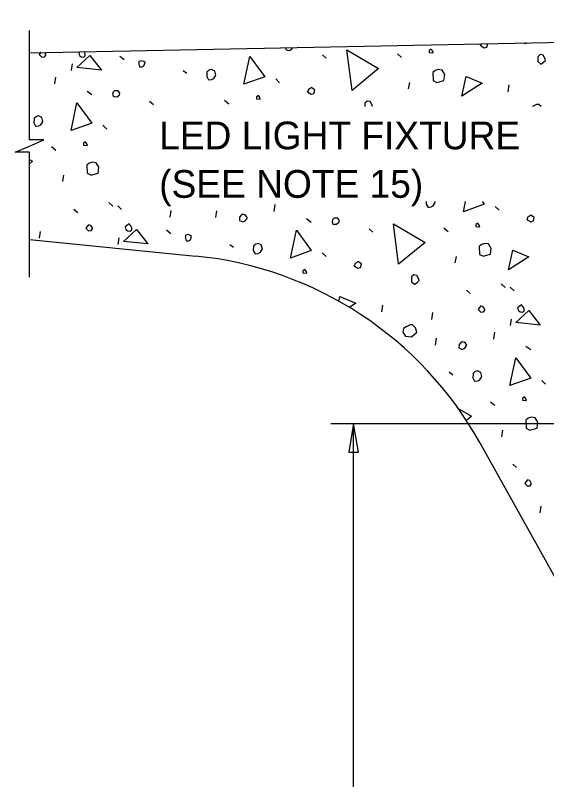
# Model space of a CAD drawing. Extents: x -1660015.2 to -1659984.9, y 2580594.2 to 2580616.7.
# Drawn here: x -1660014.771 to -1660011.876, y 2580610.058 to 2580614.22 of the extents above; entities that cross this region are included whole.
import ezdxf

# ---------------------------------------------------------------- set-up
doc = ezdxf.new("R2010")
doc.units = 0
for name, color, linetype in [('Miscellaneous', 7, 'Continuous'), ('Miscellaneous3', 7, 'Continuous'), ('SheetLines_dp', 7, 'Continuous')]:
    doc.layers.add(name, color=color, linetype=linetype)

msp = doc.modelspace()

# ---------------------------------------------------------------- linework, layer by layer
at = {"layer": 'Miscellaneous'}
for p, q in [((-1660013.4131, 2580614.0414), (-1660013.4121, 2580614.0407)), ((-1660014.2004, 2580613.9977), (-1660014.177, 2580613.9781)), ((-1660013.0968, 2580614.0035), (-1660013.0765, 2580613.9857)), ((-1660012.6894, 2580614.0092), (-1660012.666, 2580613.9896)), ((-1660014.4641, 2580613.9193), (-1660014.458, 2580613.9546)), ((-1660013.8558, 2580613.9192), (-1660013.8361, 2580613.9038)), ((-1660014.5556, 2580613.8456), (-1660014.5502, 2580613.8833)), ((-1660013.3517, 2580613.8731), (-1660013.3307, 2580613.8528)), ((-1660012.6279, 2580613.8186), (-1660012.6219, 2580613.8539)), ((-1660012.0855, 2580613.8034), (-1660012.0801, 2580613.8411)), ((-1660014.3797, 2580613.8073), (-1660014.3539, 2580613.7883)), ((-1660014.0386, 2580613.7512), (-1660014.0182, 2580613.7333)), ((-1660013.6311, 2580613.7568), (-1660013.6078, 2580613.7372)), ((-1660014.2935, 2580613.6208), (-1660014.2725, 2580613.6005)), ((-1660014.5729, 2580613.5045), (-1660014.5495, 2580613.4849)), ((-1660014.5115, 2580613.3139), (-1660014.5054, 2580613.3492)), ((-1660013.2686, 2580613.225), (-1660013.2686, 2580613.2251)), ((-1660014.4508, 2580613.1645), (-1660014.4304, 2580613.1467)), ((-1660014.2609, 2580613.1998), (-1660014.24, 2580613.1796)), ((-1660014.2121, 2580613.1819), (-1660014.1912, 2580613.1616)), ((-1660013.3602, 2580613.1513), (-1660013.3548, 2580613.189)), ((-1660012.1563, 2580613.1789), (-1660012.1353, 2580613.1586)), ((-1660013.9267, 2580613.1212), (-1660013.9206, 2580613.1564)), ((-1660013.6774, 2580613.1181), (-1660013.672, 2580613.1558)), ((-1660013.1843, 2580613.113), (-1660013.1585, 2580613.0941)), ((-1660014.6385, 2580613.0055), (-1660014.6331, 2580613.0432)), ((-1660013.9467, 2580613.0511), (-1660013.9234, 2580613.0315)), ((-1660012.8431, 2580613.0569), (-1660012.8228, 2580613.0391)), ((-1660012.4357, 2580613.0626), (-1660012.4123, 2580613.043)), ((-1660014.2104, 2580612.9727), (-1660014.2043, 2580613.008)), ((-1660013.6022, 2580612.9726), (-1660013.5825, 2580612.9572)), ((-1660013.0981, 2580612.9265), (-1660013.0771, 2580612.9062)), ((-1660012.3743, 2580612.872), (-1660012.3682, 2580612.9072)), ((-1660012.1237, 2580612.7579), (-1660012.1028, 2580612.7377)), ((-1660012.3136, 2580612.7226), (-1660012.2932, 2580612.7047)), ((-1660012.0749, 2580612.74), (-1660012.054, 2580612.7197)), ((-1660012.7737, 2580612.6045), (-1660012.7682, 2580612.6422)), ((-1660012.5013, 2580612.5636), (-1660012.4959, 2580612.6013)), ((-1660012.0732, 2580612.5308), (-1660012.0671, 2580612.566)), ((-1660012.482, 2580612.4238), (-1660012.4765, 2580612.4615)), ((-1660012.1648, 2580612.4571), (-1660012.1593, 2580612.4948)), ((-1660011.9889, 2580612.4188), (-1660011.9631, 2580612.3998)), ((-1660012.4067, 2580612.2783), (-1660012.3871, 2580612.2629)), ((-1660011.9026, 2580612.2322), (-1660011.8817, 2580612.212)), ((-1660012.1821, 2580612.116), (-1660012.1587, 2580612.0963)), ((-1660012.1206, 2580611.9254), (-1660012.1146, 2580611.9606)), ((-1660012.0599, 2580611.776), (-1660012.0396, 2580611.7581)), ((-1660011.9111, 2580611.5105), (-1660011.9057, 2580611.5481))]:
    msp.add_line(p, q, dxfattribs=at)
for points in [[(-1660013.2985, 2580614.0437), (-1660013.2988, 2580614.0426), (-1660013.2962, 2580614.0329)], [(-1660013.2962, 2580614.0329), (-1660013.2901, 2580614.0294), (-1660013.2743, 2580614.0284), (-1660013.2617, 2580614.0396), (-1660013.2601, 2580614.0445)], [(-1660012.2339, 2580614.065), (-1660012.2353, 2580614.0532), (-1660012.2366, 2580614.058)], [(-1660012.2353, 2580614.0532), (-1660012.2169, 2580614.0426), (-1660012.2024, 2580614.0465), (-1660012.1973, 2580614.0657)], [(-1660011.9947, 2580614.0633), (-1660011.9955, 2580614.0698)], [(-1660011.9867, 2580614.0699), (-1660011.9947, 2580614.0633)], [(-1660014.6402, 2580614.0067), (-1660014.626, 2580613.9924), (-1660014.6109, 2580613.9938), (-1660014.6031, 2580614.0037), (-1660014.6044, 2580614.0085), (-1660014.6103, 2580614.0175)], [(-1660014.6321, 2580614.017), (-1660014.6325, 2580614.0165), (-1660014.6402, 2580614.0067)], [(-1660014.4346, 2580613.9349), (-1660014.3641, 2580614.0004), (-1660014.3016, 2580613.9214), (-1660014.4346, 2580613.9349)], [(-1660014.4181, 2580614.0213), (-1660014.425, 2580614.0152), (-1660014.4212, 2580614.0007)], [(-1660014.4212, 2580614.0007), (-1660014.4113, 2580613.9929), (-1660014.398, 2580613.9913), (-1660014.3896, 2580613.9988), (-1660014.3898, 2580614.0091), (-1660014.3954, 2580614.0205), (-1660014.3963, 2580614.0217)], [(-1660013.5253, 2580613.8447), (-1660013.4932, 2580613.9957), (-1660013.4119, 2580613.8854), (-1660013.5253, 2580613.8447)], [(-1660012.9365, 2580613.811), (-1660012.9644, 2580614.0312), (-1660012.7923, 2580613.9298), (-1660012.9365, 2580613.811)], [(-1660012.5154, 2580614.017), (-1660012.4942, 2580614.0149), (-1660012.4968, 2580614.0245), (-1660012.5048, 2580614.0353), (-1660012.5156, 2580614.0273), (-1660012.5154, 2580614.017)], [(-1660011.9249, 2580613.9863), (-1660011.9252, 2580613.9681), (-1660011.9086, 2580613.9544), (-1660011.893, 2580613.9638), (-1660011.8828, 2580613.9742), (-1660011.8861, 2580613.9863), (-1660011.8954, 2580614.0019), (-1660011.9118, 2580614.0053), (-1660011.9244, 2580613.9941), (-1660011.9249, 2580613.9863)], [(-1660014.0977, 2580613.9527), (-1660014.0939, 2580613.9382), (-1660014.0811, 2580613.9391), (-1660014.0697, 2580613.9447), (-1660014.0639, 2580613.9618), (-1660014.0707, 2580613.9677), (-1660014.0823, 2580613.9724), (-1660014.0968, 2580613.9685), (-1660014.0977, 2580613.9527)], [(-1660013.7265, 2580613.9099), (-1660013.7279, 2580613.8862), (-1660013.7179, 2580613.8682), (-1660013.7004, 2580613.8703), (-1660013.6889, 2580613.8759), (-1660013.6783, 2580613.8943), (-1660013.6841, 2580613.916), (-1660013.7019, 2580613.9242), (-1660013.7139, 2580613.921), (-1660013.7265, 2580613.9099)], [(-1660012.4966, 2580613.9081), (-1660012.4953, 2580613.8645), (-1660012.4745, 2580613.8545), (-1660012.4624, 2580613.8577), (-1660012.4359, 2580613.8649), (-1660012.4316, 2580613.8971), (-1660012.4459, 2580613.9217), (-1660012.4648, 2580613.9244), (-1660012.4841, 2580613.9192), (-1660012.4966, 2580613.9081)], [(-1660012.338, 2580613.7798), (-1660012.315, 2580613.8869), (-1660012.2276, 2580613.8508), (-1660012.338, 2580613.7798)], [(-1660014.238, 2580613.7806), (-1660014.2318, 2580613.777), (-1660014.216, 2580613.7761), (-1660014.2035, 2580613.7872), (-1660014.2006, 2580613.7958), (-1660014.2093, 2580613.809), (-1660014.2299, 2580613.8086), (-1660014.2383, 2580613.8012), (-1660014.2405, 2580613.7902), (-1660014.238, 2580613.7806)], [(-1660013.1771, 2580613.8009), (-1660013.1587, 2580613.7902), (-1660013.1442, 2580613.7941), (-1660013.1391, 2580613.8136), (-1660013.1581, 2580613.8266), (-1660013.1664, 2580613.8192), (-1660013.1755, 2580613.8142), (-1660013.1771, 2580613.8009), (-1660013.1783, 2580613.8057)], [(-1660013.4572, 2580613.7646), (-1660013.436, 2580613.7625), (-1660013.4385, 2580613.7722), (-1660013.4466, 2580613.783), (-1660013.4574, 2580613.7749), (-1660013.4572, 2580613.7646)], [(-1660012.8248, 2580613.7225), (-1660012.8278, 2580613.734), (-1660012.8372, 2580613.7496), (-1660012.8536, 2580613.7529), (-1660012.8662, 2580613.7418), (-1660012.8666, 2580613.7339)], [(-1660014.467, 2580613.5924), (-1660014.435, 2580613.7433), (-1660014.3537, 2580613.6331), (-1660014.467, 2580613.5924)], [(-1660012.8666, 2580613.7339), (-1660012.8668, 2580613.7225)], [(-1660011.907, 2580613.7225), (-1660011.9194, 2580613.7341), (-1660011.9321, 2580613.7333), (-1660011.9526, 2580613.7226), (-1660011.9528, 2580613.7225)], [(-1660014.6683, 2580613.6575), (-1660014.6697, 2580613.6338), (-1660014.6597, 2580613.6158), (-1660014.6421, 2580613.6179), (-1660014.6307, 2580613.6236), (-1660014.6201, 2580613.642), (-1660014.6259, 2580613.6637), (-1660014.6436, 2580613.6719), (-1660014.6557, 2580613.6686), (-1660014.6683, 2580613.6575)], [(-1660014.399, 2580613.5123), (-1660014.3777, 2580613.5102), (-1660014.3803, 2580613.5198), (-1660014.3884, 2580613.5306), (-1660014.3992, 2580613.5226), (-1660014.399, 2580613.5123)], [(-1660014.6931, 2580613.4353), (-1660014.6759, 2580613.4251), (-1660014.6931, 2580613.4109)], [(-1660014.3802, 2580613.4034), (-1660014.3788, 2580613.3598), (-1660014.3581, 2580613.3498), (-1660014.346, 2580613.3531), (-1660014.3194, 2580613.3602), (-1660014.3151, 2580613.3924), (-1660014.3295, 2580613.417), (-1660014.3483, 2580613.4197), (-1660014.3676, 2580613.4145), (-1660014.3802, 2580613.4034)], [(-1660012.5317, 2580613.2051), (-1660012.5325, 2580613.1919), (-1660012.5225, 2580613.1739), (-1660012.5049, 2580613.176), (-1660012.4935, 2580613.1817), (-1660012.4829, 2580613.2), (-1660012.4842, 2580613.2051)], [(-1660012.3299, 2580613.1505), (-1660012.3183, 2580613.2051)], [(-1660012.2268, 2580613.2051), (-1660012.2165, 2580613.1912), (-1660012.3299, 2580613.1505)], [(-1660013.5489, 2580613.1215), (-1660013.5492, 2580613.1033), (-1660013.5315, 2580613.0951), (-1660013.5176, 2580613.1014), (-1660013.5064, 2580613.1173), (-1660013.5144, 2580613.1281), (-1660013.5212, 2580613.1341), (-1660013.5322, 2580613.1363), (-1660013.537, 2580613.135), (-1660013.5489, 2580613.1215)], [(-1660011.9816, 2580613.1066), (-1660011.9633, 2580613.096), (-1660011.9488, 2580613.0999), (-1660011.9436, 2580613.1194), (-1660011.9627, 2580613.1324), (-1660011.971, 2580613.125), (-1660011.98, 2580613.12), (-1660011.9816, 2580613.1066), (-1660011.9829, 2580613.1114)], [(-1660014.3865, 2580613.0601), (-1660014.3723, 2580613.0458), (-1660014.3572, 2580613.0472), (-1660014.3495, 2580613.0571), (-1660014.3508, 2580613.0619), (-1660014.3595, 2580613.0751), (-1660014.3711, 2580613.0797), (-1660014.3788, 2580613.0699), (-1660014.3865, 2580613.0601)], [(-1660014.1675, 2580613.0541), (-1660014.1577, 2580613.0463), (-1660014.1443, 2580613.0447), (-1660014.1359, 2580613.0522), (-1660014.1361, 2580613.0625), (-1660014.1418, 2580613.0739), (-1660014.1498, 2580613.0847), (-1660014.163, 2580613.076), (-1660014.1714, 2580613.0685), (-1660014.1675, 2580613.0541)], [(-1660013.0425, 2580613.0863), (-1660013.0364, 2580613.0828), (-1660013.0206, 2580613.0818), (-1660013.0081, 2580613.093), (-1660013.0052, 2580613.1015), (-1660013.0139, 2580613.1147), (-1660013.0345, 2580613.1144), (-1660013.0429, 2580613.1069), (-1660013.0451, 2580613.096), (-1660013.0425, 2580613.0863)], [(-1660012.6828, 2580612.8644), (-1660012.7108, 2580613.0846), (-1660012.5387, 2580612.9832), (-1660012.6828, 2580612.8644)], [(-1660012.2618, 2580613.0703), (-1660012.2405, 2580613.0683), (-1660012.2431, 2580613.0779), (-1660012.2512, 2580613.0887), (-1660012.262, 2580613.0807), (-1660012.2618, 2580613.0703)], [(-1660014.181, 2580612.9883), (-1660014.1105, 2580613.0538), (-1660014.0479, 2580612.9748), (-1660014.181, 2580612.9883)], [(-1660013.2716, 2580612.8981), (-1660013.2396, 2580613.049), (-1660013.1583, 2580612.9388), (-1660013.2716, 2580612.8981)], [(-1660013.8441, 2580613.0061), (-1660013.8402, 2580612.9916), (-1660013.8275, 2580612.9925), (-1660013.8161, 2580612.9981), (-1660013.8103, 2580613.0152), (-1660013.8171, 2580613.0211), (-1660013.8287, 2580613.0258), (-1660013.8431, 2580613.0219), (-1660013.8441, 2580613.0061)], [(-1660013.4728, 2580612.9633), (-1660013.4743, 2580612.9396), (-1660013.4643, 2580612.9216), (-1660013.4467, 2580612.9237), (-1660013.4353, 2580612.9293), (-1660013.4247, 2580612.9477), (-1660013.4305, 2580612.9694), (-1660013.4482, 2580612.9776), (-1660013.4603, 2580612.9744), (-1660013.4728, 2580612.9633)], [(-1660012.243, 2580612.9615), (-1660012.2416, 2580612.9179), (-1660012.2209, 2580612.9079), (-1660012.2088, 2580612.9111), (-1660012.1822, 2580612.9183), (-1660012.1779, 2580612.9505), (-1660012.1923, 2580612.9751), (-1660012.2111, 2580612.9778), (-1660012.2304, 2580612.9726), (-1660012.243, 2580612.9615)], [(-1660012.0844, 2580612.8332), (-1660012.0613, 2580612.9403), (-1660011.974, 2580612.9042), (-1660012.0844, 2580612.8332)], [(-1660012.9234, 2580612.8542), (-1660012.905, 2580612.8436), (-1660012.8905, 2580612.8475), (-1660012.8854, 2580612.867), (-1660012.9044, 2580612.88), (-1660012.9128, 2580612.8726), (-1660012.9218, 2580612.8676), (-1660012.9234, 2580612.8542), (-1660012.9247, 2580612.8591)], [(-1660013.2036, 2580612.818), (-1660013.1823, 2580612.8159), (-1660013.1849, 2580612.8256), (-1660013.193, 2580612.8364), (-1660013.2037, 2580612.8283), (-1660013.2036, 2580612.818)], [(-1660012.613, 2580612.7873), (-1660012.6133, 2580612.7691), (-1660012.5967, 2580612.7554), (-1660012.5811, 2580612.7648), (-1660012.571, 2580612.7753), (-1660012.5742, 2580612.7873), (-1660012.5836, 2580612.803), (-1660012.6, 2580612.8063), (-1660012.6125, 2580612.7952), (-1660012.613, 2580612.7873)], [(-1660013.0084, 2580612.6632), (-1660013.0031, 2580612.688), (-1660012.9158, 2580612.6518), (-1660012.9506, 2580612.6294)], [(-1660012.2493, 2580612.6182), (-1660012.2351, 2580612.6038), (-1660012.22, 2580612.6053), (-1660012.2123, 2580612.6151), (-1660012.2136, 2580612.62), (-1660012.2223, 2580612.6332), (-1660012.2339, 2580612.6378), (-1660012.2416, 2580612.628), (-1660012.2493, 2580612.6182)], [(-1660012.0303, 2580612.6121), (-1660012.0205, 2580612.6044), (-1660012.0071, 2580612.6028), (-1660011.9988, 2580612.6103), (-1660011.9989, 2580612.6206), (-1660012.0046, 2580612.632), (-1660012.0126, 2580612.6428), (-1660012.0258, 2580612.6341), (-1660012.0342, 2580612.6266), (-1660012.0303, 2580612.6121)], [(-1660012.0438, 2580612.5464), (-1660011.9733, 2580612.6119), (-1660011.9107, 2580612.5329), (-1660012.0438, 2580612.5464)], [(-1660012.659, 2580612.4954), (-1660012.6453, 2580612.4732), (-1660012.6131, 2580612.4689), (-1660012.5838, 2580612.4949), (-1660012.5903, 2580612.519), (-1660012.6076, 2580612.5351), (-1660012.6203, 2580612.5343), (-1660012.6407, 2580612.5236), (-1660012.6563, 2580612.5143), (-1660012.659, 2580612.4954)], [(-1660012.3535, 2580612.4272), (-1660012.3538, 2580612.409), (-1660012.336, 2580612.4008), (-1660012.3222, 2580612.4071), (-1660012.3109, 2580612.4231), (-1660012.319, 2580612.4339), (-1660012.3258, 2580612.4398), (-1660012.3367, 2580612.442), (-1660012.3416, 2580612.4407), (-1660012.3535, 2580612.4272)], [(-1660012.0762, 2580612.2039), (-1660012.0442, 2580612.3548), (-1660011.9629, 2580612.2446), (-1660012.0762, 2580612.2039)], [(-1660012.2774, 2580612.269), (-1660012.2788, 2580612.2453), (-1660012.2688, 2580612.2273), (-1660012.2513, 2580612.2294), (-1660012.2399, 2580612.2351), (-1660012.2293, 2580612.2534), (-1660012.2351, 2580612.2752), (-1660012.2528, 2580612.2834), (-1660012.2649, 2580612.2801), (-1660012.2774, 2580612.269)], [(-1660012.0082, 2580612.1237), (-1660011.9869, 2580612.1217), (-1660011.9895, 2580612.1313), (-1660011.9975, 2580612.1421), (-1660012.0083, 2580612.134), (-1660012.0082, 2580612.1237)], [(-1660012.3583, 2580612.0798), (-1660012.285, 2580612.0366), (-1660012.3131, 2580612.0135)], [(-1660011.9893, 2580612.0149), (-1660011.988, 2580611.9713), (-1660011.9672, 2580611.9613), (-1660011.9551, 2580611.9645), (-1660011.9286, 2580611.9717), (-1660011.9243, 2580612.0039), (-1660011.9386, 2580612.0285), (-1660011.9575, 2580612.0312), (-1660011.9768, 2580612.026), (-1660011.9893, 2580612.0149)], [(-1660011.9957, 2580611.6716), (-1660011.9815, 2580611.6572), (-1660011.9664, 2580611.6587), (-1660011.9587, 2580611.6685), (-1660011.9599, 2580611.6734), (-1660011.9687, 2580611.6866), (-1660011.9803, 2580611.6912), (-1660011.988, 2580611.6814), (-1660011.9957, 2580611.6716)]]:
    msp.add_lwpolyline(points, dxfattribs=at)
at = {"layer": 'Miscellaneous3'}
for p, q in [((-1660014.6931, 2580614.0158), (-1660004.5045, 2580614.2196)), ((-1660014.6931, 2580612.9998), (-1660013.7872, 2580612.9089)), ((-1660008.7906, 2580605.7114), (-1660012.2404, 2580611.8935))]:
    msp.add_line(p, q, dxfattribs=at)
msp.add_arc((-1660013.9869, 2580610.9189), 2, 29.163, 84.2698, dxfattribs=at)
at = {"layer": 'SheetLines_dp'}
for p, q in [((-1660013.0517, 2580611.9975), (-1660011.1723, 2580611.9975)), ((-1660012.9281, 2580606.2947), (-1660012.9281, 2580611.9975))]:
    msp.add_line(p, q, dxfattribs=at)
msp.add_lwpolyline([(-1660014.6931, 2580612.7935), (-1660014.6931, 2580613.4741), (-1660014.7706, 2580613.4741), (-1660014.6931, 2580613.5078), (-1660014.6156, 2580613.5416), (-1660014.6931, 2580613.5416), (-1660014.6931, 2580614.1372)], dxfattribs=at)
msp.add_lwpolyline([(-1660012.9281, 2580611.9974), (-1660012.9546, 2580611.8412), (-1660012.9017, 2580611.8412)], close=True, dxfattribs=at)

# ---------------------------------------------------------------- texts
for s, p in [('LED LIGHT FIXTURE ', (-1660013.9867, 2580613.4899)), ('(SEE NOTE 15)', (-1660013.9867, 2580613.2259))]:
    msp.add_text(s, height=0.1512, dxfattribs=at).set_placement(p)

doc.saveas('drawing.dxf')
